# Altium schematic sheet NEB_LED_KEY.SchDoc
size A4; Organization: Altium Limited; Address1: L3, 12a Rodborough Rd; Address2: Frenchs Forest; Address3: NSW; Address4: Australia 2086; DocumentNumber: 3; SheetNumber: 3; SheetTotal: 10
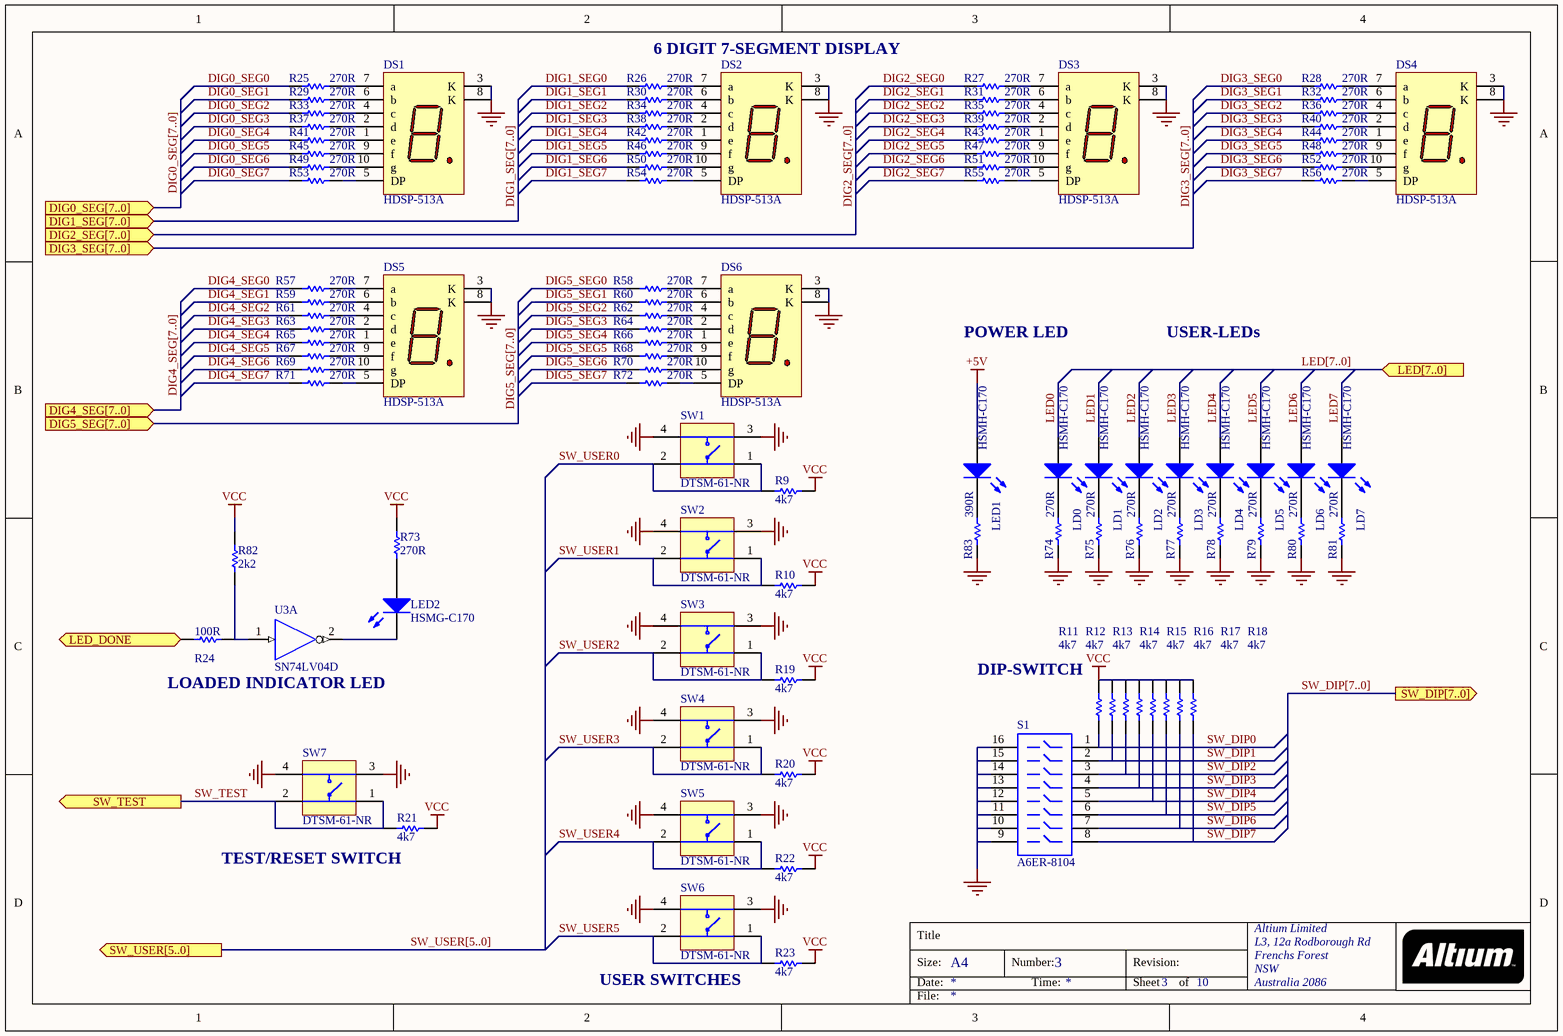
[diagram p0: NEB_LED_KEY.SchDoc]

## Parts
DS1  HDSP-513A  [SA/SC56]
DS2  HDSP-513A  [SA/SC56]
DS3  HDSP-513A  [SA/SC56]
DS4  HDSP-513A  [SA/SC56]
DS5  HDSP-513A  [SA/SC56]
DS6  HDSP-513A  [SA/SC56]
LD0  HSMH-C170  [SMD _LED]
LD1  HSMH-C170  [SMD _LED]
LD2  HSMH-C170  [SMD _LED]
LD3  HSMH-C170  [SMD _LED]
LD4  HSMH-C170  [SMD _LED]
LD5  HSMH-C170  [SMD _LED]
LD6  HSMH-C170  [SMD _LED]
LD7  HSMH-C170  [SMD _LED]
LED1  HSMH-C170  [SMD _LED]
LED2  HSMG-C170  [SMD _LED]
R9  4k7  [CR2012-0805]
R10  4k7  [CR2012-0805]
R11  4k7  [CR2012-0805]
R12  4k7  [CR2012-0805]
R13  4k7  [CR2012-0805]
R14  4k7  [CR2012-0805]
R15  4k7  [CR2012-0805]
R16  4k7  [CR2012-0805]
R17  4k7  [CR2012-0805]
R18  4k7  [CR2012-0805]
R19  4k7  [CR2012-0805]
R20  4k7  [CR2012-0805]
R21  4k7  [CR2012-0805]
R22  4k7  [CR2012-0805]
R23  4k7  [CR2012-0805]
R24  100R  [CR2012-0805]
R25  270R  [CR2012-0805]
R26  270R  [CR2012-0805]
R27  270R  [CR2012-0805]
R28  270R  [CR2012-0805]
R29  270R  [CR2012-0805]
R30  270R  [CR2012-0805]
R31  270R  [CR2012-0805]
R32  270R  [CR2012-0805]
R33  270R  [CR2012-0805]
R34  270R  [CR2012-0805]
R35  270R  [CR2012-0805]
R36  270R  [CR2012-0805]
R37  270R  [CR2012-0805]
R38  270R  [CR2012-0805]
R39  270R  [CR2012-0805]
R40  270R  [CR2012-0805]
R41  270R  [CR2012-0805]
R42  270R  [CR2012-0805]
R43  270R  [CR2012-0805]
R44  270R  [CR2012-0805]
R45  270R  [CR2012-0805]
R46  270R  [CR2012-0805]
R47  270R  [CR2012-0805]
R48  270R  [CR2012-0805]
R49  270R  [CR2012-0805]
R50  270R  [CR2012-0805]
R51  270R  [CR2012-0805]
R52  270R  [CR2012-0805]
R53  270R  [CR2012-0805]
R54  270R  [CR2012-0805]
R55  270R  [CR2012-0805]
R56  270R  [CR2012-0805]
R57  270R  [CR2012-0805]
R58  270R  [CR2012-0805]
R59  270R  [CR2012-0805]
R60  270R  [CR2012-0805]
R61  270R  [CR2012-0805]
R62  270R  [CR2012-0805]
R63  270R  [CR2012-0805]
R64  270R  [CR2012-0805]
R65  270R  [CR2012-0805]
R66  270R  [CR2012-0805]
R67  270R  [CR2012-0805]
R68  270R  [CR2012-0805]
R69  270R  [CR2012-0805]
R70  270R  [CR2012-0805]
R71  270R  [CR2012-0805]
R72  270R  [CR2012-0805]
R73  270R  [CR2012-0805]
R74  270R  [CR2012-0805]
R75  270R  [CR2012-0805]
R76  270R  [CR2012-0805]
R77  270R  [CR2012-0805]
R78  270R  [CR2012-0805]
R79  270R  [CR2012-0805]
R80  270R  [CR2012-0805]
R81  270R  [CR2012-0805]
R82  2k2  [CR2012-0805]
R83  390R  [CR2012-0805]
S1  A6ER-8104  [DIP-16-KEY]
SW1  DTSM-61-NR  [B3FS_SWITCH]
SW2  DTSM-61-NR  [B3FS_SWITCH]
SW3  DTSM-61-NR  [B3FS_SWITCH]
SW4  DTSM-61-NR  [B3FS_SWITCH]
SW5  DTSM-61-NR  [B3FS_SWITCH]
SW6  DTSM-61-NR  [B3FS_SWITCH]
SW7  DTSM-61-NR  [B3FS_SWITCH]
U3  SN74LV04D  [D014]  (part A of 6)

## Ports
DIG0_SEG[7..0] (in), DIG1_SEG[7..0] (in), DIG2_SEG[7..0] (in), DIG3_SEG[7..0] (in), DIG4_SEG[7..0] (in), DIG5_SEG[7..0] (in), LED[7..0] (in), LED_DONE (in), SW_DIP[7..0] (out), SW_TEST (out), SW_USER[5..0] (out)

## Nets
+5V: LED1.1(A)
GND: DS1.3(K) DS1.8(K) DS2.3(K) DS2.8(K) DS3.3(K) DS3.8(K) DS4.3(K) DS4.8(K) DS5.3(K) DS5.8(K) DS6.3(K) DS6.8(K) R74.1 R75.1 R76.1 R77.1 R78.1 R79.1 R80.1 R81.1 R83.1 S1.9 S1.10 S1.11 S1.12 S1.13 S1.14 S1.15 S1.16 SW1.3 SW1.4 SW2.3 SW2.4 SW3.3 SW3.4 SW4.3 SW4.4 SW5.3 SW5.4 SW6.3 SW6.4 SW7.3 SW7.4 U3.7(GND)
VCC: R9.1 R10.1 R11.2 R12.2 R13.2 R14.2 R15.2 R16.2 R17.2 R18.2 R19.1 R20.1 R21.1 R22.1 R23.1 R73.2 R82.1 U3.14(VCC)
DIG0_SEG0: R25.2
DIG0_SEG1: R29.2
DIG0_SEG2: R33.2
DIG0_SEG3: R37.2
DIG0_SEG4: R41.2
DIG0_SEG5: R45.2
DIG0_SEG6: R49.2
DIG0_SEG7: R53.2
DIG1_SEG0: R26.2
DIG1_SEG1: R30.2
DIG1_SEG2: R34.2
DIG1_SEG3: R38.2
DIG1_SEG4: R42.2
DIG1_SEG5: R46.2
DIG1_SEG6: R50.2
DIG1_SEG7: R54.2
DIG2_SEG0: R27.2
DIG2_SEG1: R31.2
DIG2_SEG2: R35.2
DIG2_SEG3: R39.2
DIG2_SEG4: R43.2
DIG2_SEG5: R47.2
DIG2_SEG6: R51.2
DIG2_SEG7: R55.2
DIG3_SEG0: R28.2
DIG3_SEG1: R32.2
DIG3_SEG2: R36.2
DIG3_SEG3: R40.2
DIG3_SEG4: R44.2
DIG3_SEG5: R48.2
DIG3_SEG6: R52.2
DIG3_SEG7: R56.2
DIG4_SEG0: R57.2
DIG4_SEG1: R59.2
DIG4_SEG2: R61.2
DIG4_SEG3: R63.2
DIG4_SEG4: R65.2
DIG4_SEG5: R67.2
DIG4_SEG6: R69.2
DIG4_SEG7: R71.2
DIG5_SEG0: R58.2
DIG5_SEG1: R60.2
DIG5_SEG2: R62.2
DIG5_SEG3: R64.2
DIG5_SEG4: R66.2
DIG5_SEG5: R68.2
DIG5_SEG6: R70.2
DIG5_SEG7: R72.2
LED0: LD0.1(A)
LED1: LD1.1(A)
LED2: LD2.1(A)
LED3: LD3.1(A)
LED4: LD4.1(A)
LED5: LD5.1(A)
LED6: LD6.1(A)
LED7: LD7.1(A)
LED_DONE: R24.1 ; port LED_DONE
SW_DIP0: R11.1 S1.1
SW_DIP1: R12.1 S1.2
SW_DIP2: R13.1 S1.3
SW_DIP3: R14.1 S1.4
SW_DIP4: R15.1 S1.5
SW_DIP5: R16.1 S1.6
SW_DIP6: R17.1 S1.7
SW_DIP7: R18.1 S1.8
SW_TEST: R21.2 SW7.1 SW7.2 ; port SW_TEST
SW_USER0: R9.2 SW1.1 SW1.2
SW_USER1: R10.2 SW2.1 SW2.2
SW_USER2: R19.2 SW3.1 SW3.2
SW_USER3: R20.2 SW4.1 SW4.2
SW_USER4: R22.2 SW5.1 SW5.2
SW_USER5: R23.2 SW6.1 SW6.2
NetDS1_1: DS1.1(e) R41.1
NetDS1_2: DS1.2(d) R37.1
NetDS1_4: DS1.4(c) R33.1
NetDS1_5: DS1.5(DP) R53.1
NetDS1_6: DS1.6(b) R29.1
NetDS1_7: DS1.7(a) R25.1
NetDS1_9: DS1.9(f) R45.1
NetDS1_10: DS1.10(g) R49.1
NetDS2_1: DS2.1(e) R42.1
NetDS2_2: DS2.2(d) R38.1
NetDS2_4: DS2.4(c) R34.1
NetDS2_5: DS2.5(DP) R54.1
NetDS2_6: DS2.6(b) R30.1
NetDS2_7: DS2.7(a) R26.1
NetDS2_9: DS2.9(f) R46.1
NetDS2_10: DS2.10(g) R50.1
NetDS3_1: DS3.1(e) R43.1
NetDS3_2: DS3.2(d) R39.1
NetDS3_4: DS3.4(c) R35.1
NetDS3_5: DS3.5(DP) R55.1
NetDS3_6: DS3.6(b) R31.1
NetDS3_7: DS3.7(a) R27.1
NetDS3_9: DS3.9(f) R47.1
NetDS3_10: DS3.10(g) R51.1
NetDS4_1: DS4.1(e) R44.1
NetDS4_2: DS4.2(d) R40.1
NetDS4_4: DS4.4(c) R36.1
NetDS4_5: DS4.5(DP) R56.1
NetDS4_6: DS4.6(b) R32.1
NetDS4_7: DS4.7(a) R28.1
NetDS4_9: DS4.9(f) R48.1
NetDS4_10: DS4.10(g) R52.1
NetDS5_1: DS5.1(e) R65.1
NetDS5_2: DS5.2(d) R63.1
NetDS5_4: DS5.4(c) R61.1
NetDS5_5: DS5.5(DP) R71.1
NetDS5_6: DS5.6(b) R59.1
NetDS5_7: DS5.7(a) R57.1
NetDS5_9: DS5.9(f) R67.1
NetDS5_10: DS5.10(g) R69.1
NetDS6_1: DS6.1(e) R66.1
NetDS6_2: DS6.2(d) R64.1
NetDS6_4: DS6.4(c) R62.1
NetDS6_5: DS6.5(DP) R72.1
NetDS6_6: DS6.6(b) R60.1
NetDS6_7: DS6.7(a) R58.1
NetDS6_9: DS6.9(f) R68.1
NetDS6_10: DS6.10(g) R70.1
NetLD0_2: LD0.2(K) R74.2
NetLD1_2: LD1.2(K) R75.2
NetLD2_2: LD2.2(K) R76.2
NetLD3_2: LD3.2(K) R77.2
NetLD4_2: LD4.2(K) R78.2
NetLD5_2: LD5.2(K) R79.2
NetLD6_2: LD6.2(K) R80.2
NetLD7_2: LD7.2(K) R81.2
NetLED1_2: LED1.2(K) R83.2
NetLED2_1: LED2.1(A) R73.1
NetLED2_2: LED2.2(K) U3.2(Y)
NetR24_2: R24.2 R82.2 U3.1(A)

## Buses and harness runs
bus DIG0_SEG[7..0] = port DIG0_SEG[7..0]
bus DIG1_SEG[7..0] = port DIG1_SEG[7..0]
bus DIG2_SEG[7..0] = port DIG2_SEG[7..0]
bus DIG3_SEG[7..0] = port DIG3_SEG[7..0]
bus DIG4_SEG[7..0] = port DIG4_SEG[7..0]
bus DIG5_SEG[7..0] = port DIG5_SEG[7..0]
bus LED[7..0] = port LED[7..0]
bus SW_DIP[7..0] = port SW_DIP[7..0]
bus SW_USER[5..0] = port SW_USER[5..0]

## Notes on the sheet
- 6 DIGIT 7-SEGMENT DISPLAY
- POWER LED
- USER-LEDs
- LOADED INDICATOR LED
- DIP-SWITCH
- TEST/RESET SWITCH
- (near SW6) USER SWITCHES

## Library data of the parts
DS1-DS6 = HDSP-513A: 14.2 mm General Purpose 7-Segment Display: CC, RH DP; Package Information: Latest Revision: 25-Jul-2001; Min. Intensity: 3201 ucd; Note: IF = 10 mA; Colour: AlGaAs Red
LD0-LD7 LED1 = HSMX-C670: Typical RED GaAs SMD LED Agilent make; Manufacturer: Generic Components; Class I: Optoelectronic; Fitted: True
LED2 = HSMX-C670: Typical GREEN GaAs SMD LED Agilent make; Manufacturer: Generic Components; Class I: Optoelectronic; Fitted: True
R9-R23 R25-R72 R74-R81 R83 = RES: Resistor; Fitted: True
R24 R73 R82 = RES: Resistor
S1 = A6ER-8104: DIP Switch Side actuator long liver Piano Key; Manufacturer: Generic Components; Fitted: True
SW1-SW7 = B3FS: SPNA SMD Keyboard Switch; Fitted: True
U3 = SN74LV04D: Hex Inverter; Package Information: Latest Revision: Jan-1998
